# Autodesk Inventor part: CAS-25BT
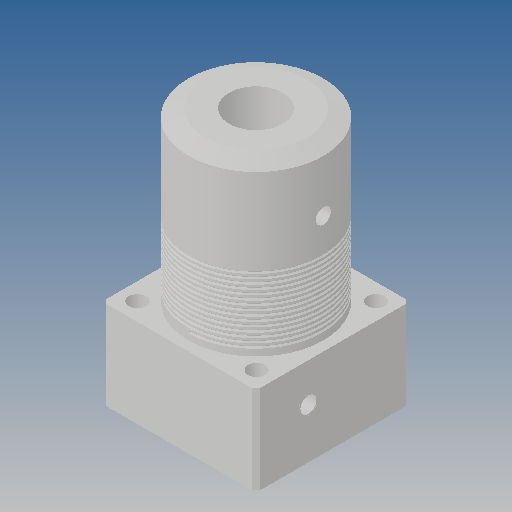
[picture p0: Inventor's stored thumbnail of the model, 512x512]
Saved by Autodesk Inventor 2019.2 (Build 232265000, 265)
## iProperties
Created: 2010-02
Part Number: CAS-25BT
Material: Ogólny
Document SubType Name: Modeling
Designer: CADENGINEERING4
Density: 1 g/cm^3
Appearance: Domyślna
Author: CADENGINEERING4
Revision Number: 2LAST_VERSION
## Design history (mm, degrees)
feature "Baza1"
feature "Powierzchnia1"
node "Bryła1"
body "Srf1"
